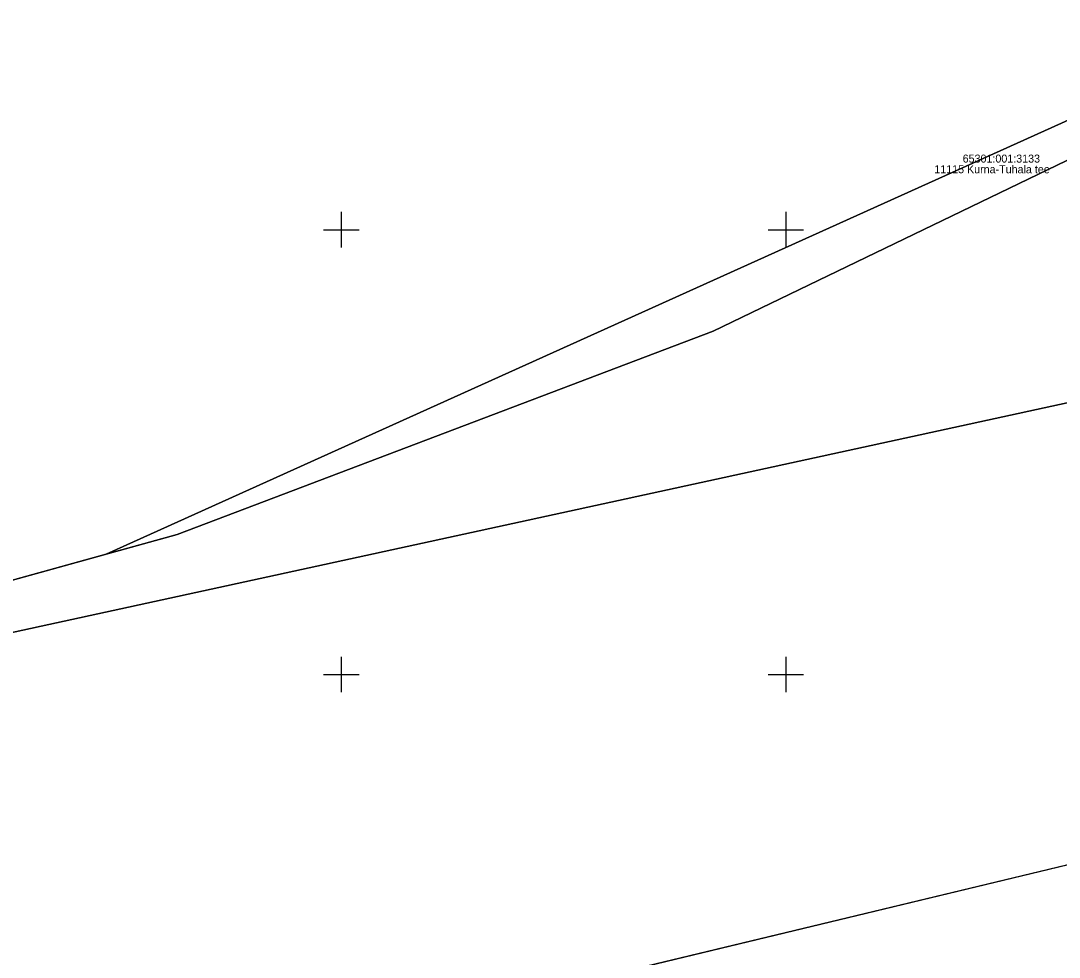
# Model space of a CAD drawing. Extents: x 543497 to 552146, y 6567125 to 6579845.
# Drawn here: x 546664 to 546780.8, y 6577818.2 to 6577923.5 of the extents above; entities that cross this region are included whole.
import ezdxf

# ---------------------------------------------------------------- set-up
doc = ezdxf.new("R2010")
doc.units = 0
doc.layers.add('xref_Kangru tee 1_geodeesia$0$PIIR', color=7, linetype='Continuous')
doc.layers.add('xref_Kangru tee 1_geodeesia$0$vork', color=7, linetype='Continuous')

# ---------------------------------------------------------------- blocks, each defined once
blk = doc.blocks.new('xref_Kangru tee 1_geodeesia$0$VKORIS')
for p, q in [((0, 4), (0, -4)), ((-4, 0), (4, 0))]:
    blk.add_line(p, q)

msp = doc.modelspace()

# ---------------------------------------------------------------- linework, layer by layer
at = {"layer": 'xref_Kangru tee 1_geodeesia$0$PIIR'}
for points in [[(546948.2, 6577919.45), (546801.95, 6577884.96), (546612.83, 6577843.82), (546611.48, 6577846.34), (546681.56, 6577865.74), (546741.83, 6577888.61), (546804.12, 6577918.64), (546823.72, 6577935.62), (546840.87, 6577968.94), (546842.58, 6578000.95), (546830.7, 6578057.64), (546794.77, 6578166.4), (546728.27, 6578308.16), (546677.39, 6578395.18), (546581.04, 6578525.99)], [(546479.96, 6578264.05), (546660.75, 6578417.77), (546677.39, 6578395.18), (546728.27, 6578308.16), (546794.77, 6578166.4), (546830.7, 6578057.64), (546842.58, 6578000.95), (546840.87, 6577968.94), (546792.14, 6577916.99), (546673.57, 6577863.53), (546611.48, 6577846.34), (546521.16, 6578099.75), (546496.8, 6578164.74), (546476.38, 6578219.21), (546479.96, 6578264.05)], [(546673.57, 6577863.53), (546792.14, 6577916.99), (546840.87, 6577968.94), (546823.72, 6577935.62), (546804.12, 6577918.64), (546741.83, 6577888.61), (546681.56, 6577865.74), (546673.57, 6577863.53)], [(547009.94, 6577883.45), (546729.34, 6577816.03), (546702.66, 6577807.95), (546633.51, 6577792.62), (546622.52, 6577814.88), (546612.83, 6577843.82), (546801.95, 6577884.96), (546948.2, 6577919.45)], [(546729.34, 6577816.03), (546952.06, 6577869.63), (546981.71, 6577772.45), (546959.14, 6577767.02), (546924.09, 6577758.51), (546773.43, 6577722.06), (546729.34, 6577816.03)]]:
    msp.add_lwpolyline(points, dxfattribs=at)

# ---------------------------------------------------------------- block references
at = {"layer": 'xref_Kangru tee 1_geodeesia$0$vork', "xscale": 0.5, "yscale": 0.5}
for p in [(546700, 6577900), (546750, 6577900), (546700, 6577850), (546750, 6577850)]:
    msp.add_blockref('xref_Kangru tee 1_geodeesia$0$VKORIS', p, dxfattribs=at)

# ---------------------------------------------------------------- texts
at = {"layer": 'xref_Kangru tee 1_geodeesia$0$PIIR'}
for s, p in [('65301:001:3133', (546769.89, 6577907.54)), ('11115 Kurna-Tuhala tee', (546766.7, 6577906.34))]:
    msp.add_text(s, height=0.9, dxfattribs=at).set_placement(p)

doc.saveas('drawing.dxf')
